AutomationDirect Productivity Suite project: SSW900 adpro (software 4.2.0 (39))
author: fguedez
Rung notation: left to right = series (deeper-indented lines continue the line above), [a | b] = parallel branches, -- = plain wire, BOX.Pin = further input of the box above; 'quoted' = tag name, ? = field left empty; instruction and field names as stored in the project; options that are off are not listed.

HARDWARE
  EtherNet/IP device: E/IP Scanner "SSW900"
    with: SSW900-CETH-W "SSW900"
  Base 1 (5 slots)
    slot 0: P2-550
    slot 1: P2-HSI "P2-HSI-0.1.1"
    slot 2: P2-HSO "P2-HSO-0.1.2"
    slot 3: P2-08SIM

TAGS  (name : type @system ID = initial value)
  'EC Done' : Boolean @C-000183
  'Error Counter' : Int32 @S32-000129
  'IC Done' : Boolean @C-000214
  'Interlock Counter' : Int32 @S32-000131
  'Modbus RTU' : Boolean @C-000266
  'Modbus TCP' : Boolean @C-000304
  'Success Counter' : Int32 @S32-000130
  'Success Done' : Boolean @C-000111
  TimedC : Boolean @C-000225
  'EIP Implicit' : Boolean @C-000428
  'EIP Explicit' : Boolean @C-000429
  'StatusWord P680' : Int16 @S16-000037
  'Optional parameter' : Int16 @S16-000040
  Reserved : Boolean @C-000495
  'StatusWord P680 N2' : Int16 @S16-000041
  'Control Word P684 N2' : Int16 @S16-000042
  'Speed Reference P685 N2' : Int16 @S16-000043
  'Motor Speed P681 N2' : Int16 @S16-000044
  ExplDataIn1 : Array[1] of Int16 @AR1S16-000005
  ExplDataIn2 : Array[1] of Int16 @AR1S16-000006
  ExplDataOut4 : Array[1] of Int16 @AR1S16-000008
  ExplDataOut3 : Array[1] of Int16 @AR1S16-000009
  ExtStst1 : Array[1] of Uint16 @AR1US16-000001
  ExtStst2 : Array[1] of Uint16 @AR1US16-000002
  ExtStst3 : Array[1] of Uint16 @AR1US16-000003
  ExtStst4 : Array[1] of Uint16 @AR1US16-000004
  'Control Word P682' : Uint16 @US16-000014
  'Speed Reference P683' : Int16 @S16-000045
  'Control Word P682 N2' : Uint16 @US16-000015
  'Speed Reference P683 N2' : Int16 @S16-000046
  'Motor Speed HZ' : Int16 @S16-000050
  'Freq CMD Hz' : Int16 @S16-000047
  'Motor Speed HZ N2' : Int16 @S16-000048
  'Freq CMD Hz N2' : Int16 @S16-000049
  'StatusWord P679' : Uint16 @US16-000018
  'Control Word P685' : Uint16 @US16-000016
  'StatusWord P679 N2' : Uint16 @US16-000017
  'Control Word P685 N2' : Uint16 @US16-000019
  'SSW900 Braking' : Boolean @C-000567
  'SSW900 Bypass' : Boolean @C-000568
  'SSW900 Configuration' : Boolean @C-000569
  'SSW900 Fault' : Boolean @C-000570
  'SSW900 Full Voltage' : Boolean @C-000571
  'SSW900 FWD/REV' : Boolean @C-000572
  'SSW900 Initial Test' : Boolean @C-000573
  'SSW900 Jog' : Boolean @C-000574
  'SSW900 Ramp down' : Boolean @C-000575
  'SSW900 Ramp up' : Boolean @C-000576
  'SSW900 Ready' : Boolean @C-000577
  'SSW900 Restart Delay' : Boolean @C-000578
  'SSW900 Start Delay' : Boolean @C-000579
  'SSW900Genearl Disabled' : Boolean @C-000580
  'SSW900 Alarm' : Boolean @C-000581
  'SSW900 Brakingg' : Boolean @C-000582
  'SSW900 Bypasss' : Boolean @C-000583
  'SSW900 Faultt' : Boolean @C-000584
  'SSW900 Full Voltagee' : Boolean @C-000585
  'SSW900 FWD/REVV' : Boolean @C-000586
  'SSW900 Gen Enabled' : Boolean @C-000587
  'SSW900 Initial Testt' : Boolean @C-000588
  'SSW900 Jogg' : Boolean @C-000589
  'SSW900 Ramp downn' : Boolean @C-000590
  'SSW900 Ramp Upp' : Boolean @C-000591
  'SSW900 Remote' : Boolean @C-000592
  'SSW900 Reverse' : Boolean @C-000593
  'SSW900 Running' : Boolean @C-000594
  'SSW900 Toff' : Boolean @C-000595
  'SSW900 Ton' : Boolean @C-000596
  'SSW900 FWD/REV CMD' : Boolean @C-000597
  'SSW900 Gen Enable MD' : Boolean @C-000598
  'SSW900 JOG CMD' : Boolean @C-000599
  'SSW900 LOC/REM CMD' : Boolean @C-000600
  'SSW900 Reset' : Boolean @C-000601
  'SSW900 Start Stop CMD' : Boolean @C-000602
  'SSW900 Braking N2' : Boolean @C-000603
  'SSW900 Bypass N2' : Boolean @C-000604
  'SSW900 Configuration N2' : Boolean @C-000605
  'SSW900 Fault N2' : Boolean @C-000606
  'SSW900 Full Voltage N2' : Boolean @C-000607
  'SSW900 FWD/REV N2' : Boolean @C-000608
  'SSW900 Initial Test N2' : Boolean @C-000609
  'SSW900 Jog N2' : Boolean @C-000610
  'SSW900 Ramp down N2' : Boolean @C-000611
  'SSW900 Ramp up N2' : Boolean @C-000612
  'SSW900 Ready N2' : Boolean @C-000613
  'SSW900 Restart Delay N2' : Boolean @C-000614
  'SSW900 Start Delay N2' : Boolean @C-000615
  'SSW900Genearl Disabled N2' : Boolean @C-000616
  'SSW900 Alarm N2' : Boolean @C-000617
  'SSW900 Brakingg N2' : Boolean @C-000618
  'SSW900 Bypasss N2' : Boolean @C-000619
  'SSW900 Faultt N2' : Boolean @C-000620
  'SSW900 Full Voltagee N2' : Boolean @C-000621
  'SSW900 FWD/REVV N2' : Boolean @C-000622
  'SSW900 Gen Enabled N2' : Boolean @C-000623
  'SSW900 Initial Testt N2' : Boolean @C-000624
  'SSW900 Jogg N2' : Boolean @C-000625
  'SSW900 Ramp downn N2' : Boolean @C-000626
  'SSW900 Ramp Upp N2' : Boolean @C-000627
  'SSW900 Remote N2' : Boolean @C-000628
  'SSW900 Reverse N2' : Boolean @C-000629
  'SSW900 Running N2' : Boolean @C-000630
  'SSW900 Toff N2' : Boolean @C-000631
  'SSW900 Ton N2' : Boolean @C-000632
  'SSW900 FWD/REV CMD N2' : Boolean @C-000633
  'SSW900 Gen Enable MD N2' : Boolean @C-000634
  'SSW900 JOG CMD N2' : Boolean @C-000635
  'SSW900 Reset N2' : Boolean @C-000636
  'SSW900 Start Stop CMD N2' : Boolean @C-000637
  'SSW900 Data In' : Array[1] of Uint16 @AR1US16-000005
  'SSW900 Data Out' : Array[1] of Uint16 @AR1US16-000006
  Test : Array[16] of Boolean @AR1C-000001

SYSTEM TAGS USED OR MAPPED TO MODBUS
  'Always Off Bit' : Boolean @SBR-001002  // always off
  EXp1 : EMSG @SSTRUC-000031  // System Structure for EtherNet/IP Explicit Message
  EXp3 : EMSG @SSTRUC-000033  // System Structure for EtherNet/IP Explicit Message
  'SSW900 Node1 Read' : MRX @SSTRUC-000044  // System Structure for Modbus Read
  'SSW900 Node1 Write' : MWX @SSTRUC-000045  // System Structure for Modbus Write
  'SSW900 Node2 Read' : MRX @SSTRUC-000046  // System Structure for Modbus Read
  'SSW900 Node2 Write' : MWX @SSTRUC-000047  // System Structure for Modbus Write

TASK Main  (Run Every Scan)
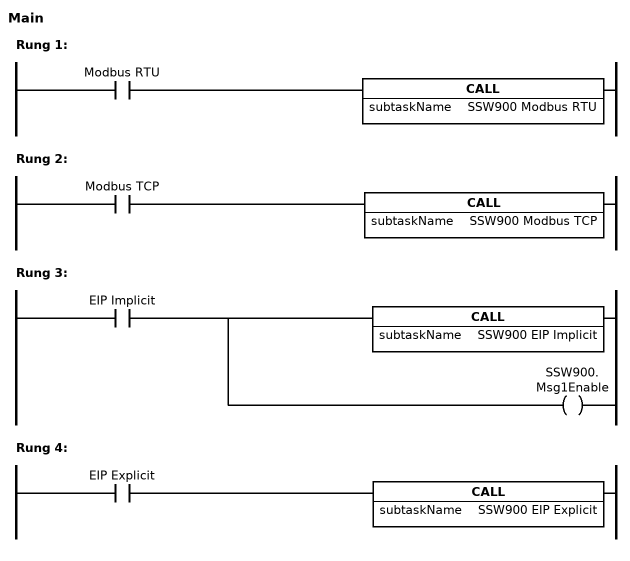
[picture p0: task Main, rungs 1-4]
Rung 1:
  NO('Modbus RTU') CALL('SSW900 Modbus RTU')
Rung 2:
  NO('Modbus TCP') CALL('SSW900 Modbus TCP')
Rung 3:
  NO('EIP Implicit') [CALL('SSW900 EIP Implicit') | OUT(SSW900.Msg1Enable)]
Rung 4:
  NO('EIP Explicit') CALL('SSW900 EIP Explicit')

TASK 'SSW900 Modbus RTU'  (Run When Called)
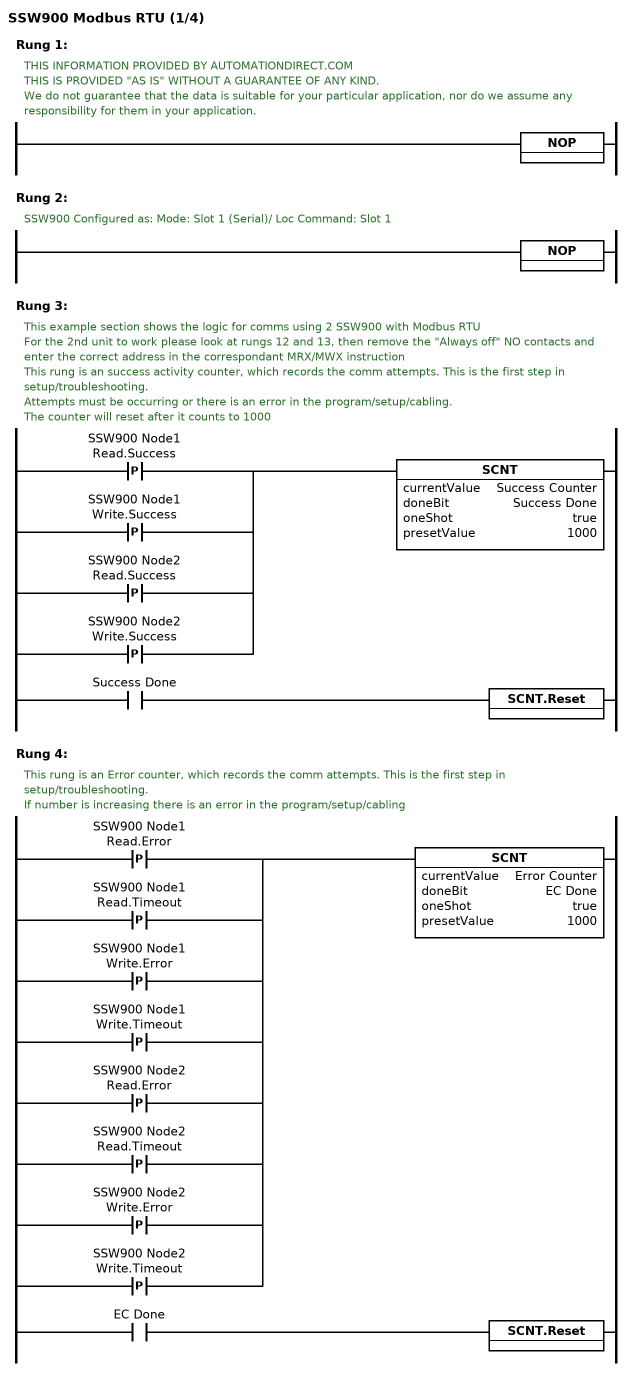
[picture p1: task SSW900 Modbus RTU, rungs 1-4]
Rung 1:
  // THIS INFORMATION PROVIDED BY AUTOMATIONDIRECT.COM
  // THIS IS PROVIDED "AS IS" WITHOUT A GUARANTEE OF ANY KIND.
  // We do not guarantee that the data is suitable for your particular application, nor do we assume any responsibility for them in your application.
  NOP()
Rung 2:
  // SSW900 Configured as: Mode: Slot 1 (Serial)/ Loc Command: Slot 1
  NOP()
Rung 3:
  // This example section shows the logic for comms using 2 SSW900 with Modbus RTU
  // For the 2nd unit to work please look at rungs 12 and 13, then remove the "Always off" NO contacts and enter the correct address in the correspondant MRX/MWX instruction
  // This rung is an success activity counter, which records the comm attempts. This is the first step in setup/troubleshooting.
  // Attempts must be occurring or there is an error in the program/setup/cabling.
  // The counter will reset after it counts to 1000
  [ NOE('SSW900 Node1 Read.Success', rising)
    | NOE('SSW900 Node1 Write.Success', rising)
    | NOE('SSW900 Node2 Read.Success', rising)
    | NOE('SSW900 Node2 Write.Success', rising) ]
    SCNT(currentValue='Success Counter', doneBit='Success Done', oneShot, presetValue=1000)
  NO('Success Done') SCNT.Reset
Rung 4:
  // This rung is an Error counter, which records the comm attempts. This is the first step in setup/troubleshooting.
  // If number is increasing there is an error in the program/setup/cabling
  [ NOE('SSW900 Node1 Read.Error', rising)
    | NOE('SSW900 Node1 Read.Timeout', rising)
    | NOE('SSW900 Node1 Write.Error', rising)
    | NOE('SSW900 Node1 Write.Timeout', rising)
    | NOE('SSW900 Node2 Read.Error', rising)
    | NOE('SSW900 Node2 Read.Timeout', rising)
    | NOE('SSW900 Node2 Write.Error', rising)
    | NOE('SSW900 Node2 Write.Timeout', rising) ]
    SCNT(currentValue='Error Counter', doneBit='EC Done', oneShot, presetValue=1000)
  NO('EC Done') SCNT.Reset
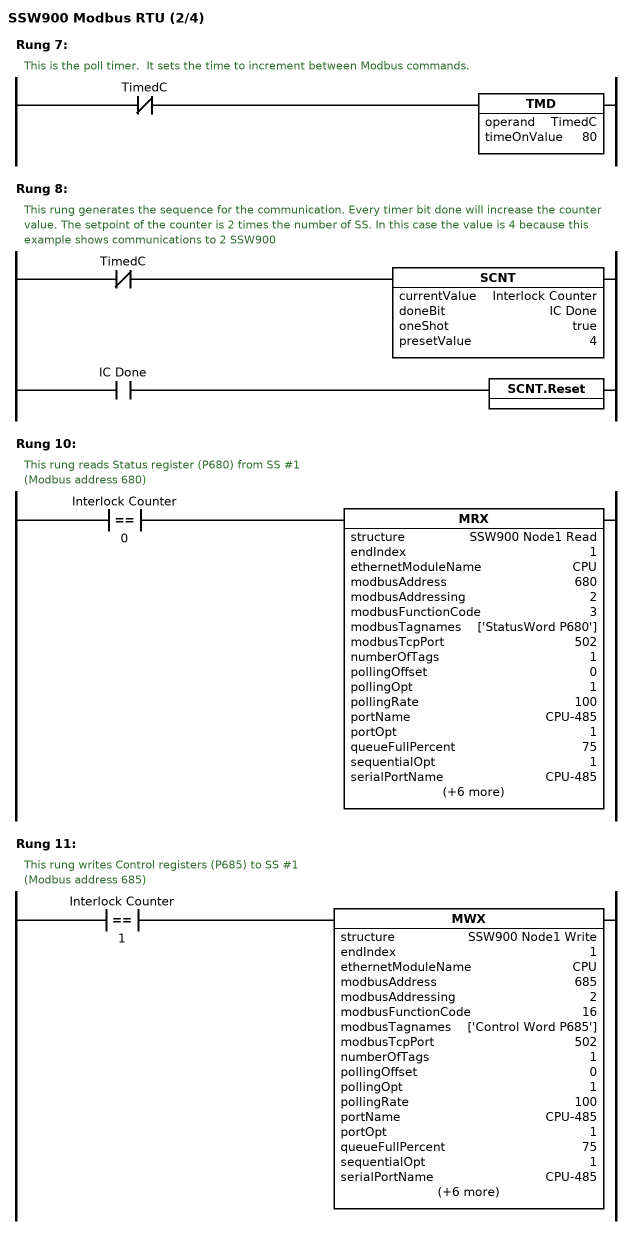
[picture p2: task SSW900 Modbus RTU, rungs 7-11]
Rung 7:
  // This is the poll timer.  It sets the time to increment between Modbus commands.
  NC(TimedC) TMD(TimedC, timeOnValue=80)
Rung 8:
  // This rung generates the sequence for the communication. Every timer bit done will increase the counter value. The setpoint of the counter is 2 times the number of SS. In this case the value is 4 because this example shows communications to 2 SSW900
  NC(TimedC) SCNT(currentValue='Interlock Counter', doneBit='IC Done', oneShot, presetValue=4)
  NO('IC Done') SCNT.Reset
Rung 10:
  // This rung reads Status register (P680) from SS #1
  // (Modbus address 680)
  COMP('Interlock Counter' = 0)
    MRX(structure='SSW900 Node1 Read', endIndex=1, ethernetModuleName=CPU, modbusAddress=680, modbusAddressing=2, modbusFunctionCode=3, modbusTagnames=['StatusWord P680'], modbusTcpPort=502, numberOfTags=1, pollingOffset=0, pollingOpt=1, pollingRate=100, portName=CPU-485, portOpt=1, queueFullPercent=75, sequentialOpt=1, serialPortName=CPU-485, slaveEthernetNodeNum=255, slaveIpAddress=10.10.112.59, slaveSerialNodeNum=1, startingIndex=1, stringLength=2, wordSwap)
Rung 11:
  // This rung writes Control registers (P685) to SS #1
  // (Modbus address 685)
  COMP('Interlock Counter' = 1)
    MWX(structure='SSW900 Node1 Write', endIndex=1, ethernetModuleName=CPU, modbusAddress=685, modbusAddressing=2, modbusFunctionCode=16, modbusTagnames=['Control Word P685'], modbusTcpPort=502, numberOfTags=1, pollingOffset=0, pollingOpt=1, pollingRate=100, portName=CPU-485, portOpt=1, queueFullPercent=75, sequentialOpt=1, serialPortName=CPU-485, slaveEthernetNodeNum=255, slaveIpAddress=10.10.112.59, slaveSerialNodeNum=1, startingIndex=1, stringLength=2, wordSwap)
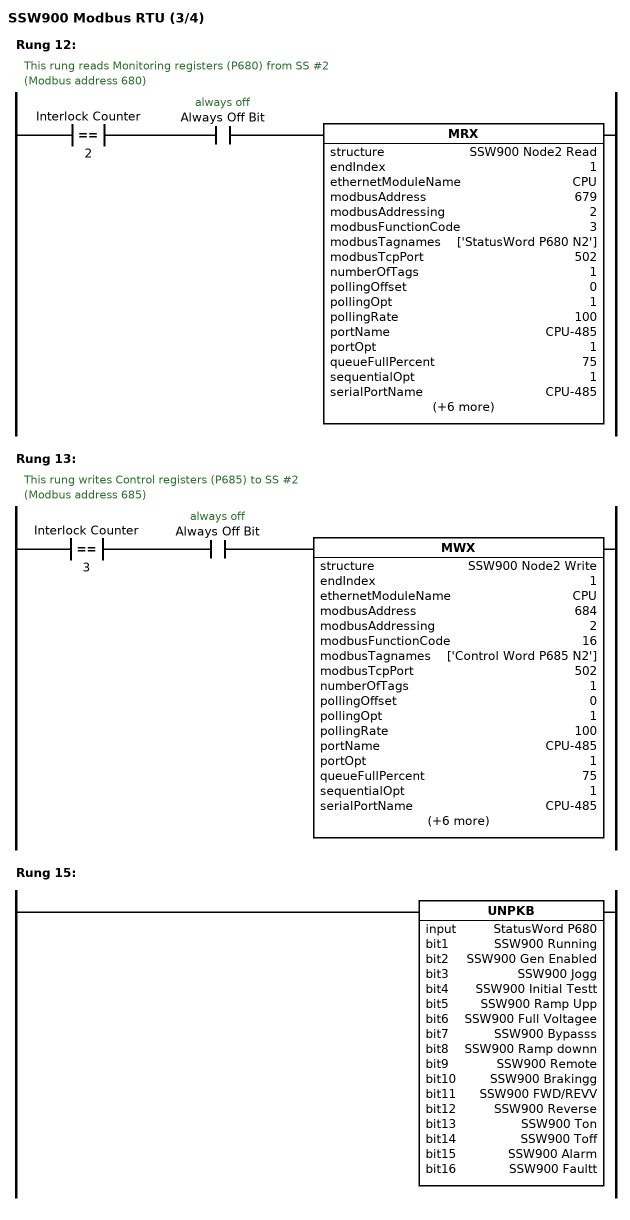
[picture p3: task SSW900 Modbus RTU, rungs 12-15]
Rung 12:
  // This rung reads Monitoring registers (P680) from SS #2
  // (Modbus address 680)
  COMP('Interlock Counter' = 2) NO('Always Off Bit')
    MRX(structure='SSW900 Node2 Read', endIndex=1, ethernetModuleName=CPU, modbusAddress=679, modbusAddressing=2, modbusFunctionCode=3, modbusTagnames=['StatusWord P680 N2'], modbusTcpPort=502, numberOfTags=1, pollingOffset=0, pollingOpt=1, pollingRate=100, portName=CPU-485, portOpt=1, queueFullPercent=75, sequentialOpt=1, serialPortName=CPU-485, slaveEthernetNodeNum=255, slaveIpAddress=10.10.112.59, slaveSerialNodeNum=2, startingIndex=1, stringLength=2, wordSwap)
Rung 13:
  // This rung writes Control registers (P685) to SS #2
  // (Modbus address 685)
  COMP('Interlock Counter' = 3) NO('Always Off Bit')
    MWX(structure='SSW900 Node2 Write', endIndex=1, ethernetModuleName=CPU, modbusAddress=684, modbusAddressing=2, modbusFunctionCode=16, modbusTagnames=['Control Word P685 N2'], modbusTcpPort=502, numberOfTags=1, pollingOffset=0, pollingOpt=1, pollingRate=100, portName=CPU-485, portOpt=1, queueFullPercent=75, sequentialOpt=1, serialPortName=CPU-485, slaveEthernetNodeNum=255, slaveIpAddress=10.10.112.59, slaveSerialNodeNum=2, startingIndex=1, stringLength=2, wordSwap)
Rung 15:
  UNPKB(input='StatusWord P680', bit1='SSW900 Running', bit2='SSW900 Gen Enabled', bit3='SSW900 Jogg', bit4='SSW900 Initial Testt', bit5='SSW900 Ramp Upp', bit6='SSW900 Full Voltagee', bit7='SSW900 Bypasss', bit8='SSW900 Ramp downn', bit9='SSW900 Remote', bit10='SSW900 Brakingg', bit11='SSW900 FWD/REVV', bit12='SSW900 Reverse', bit13='SSW900 Ton', bit14='SSW900 Toff', bit15='SSW900 Alarm', bit16='SSW900 Faultt')
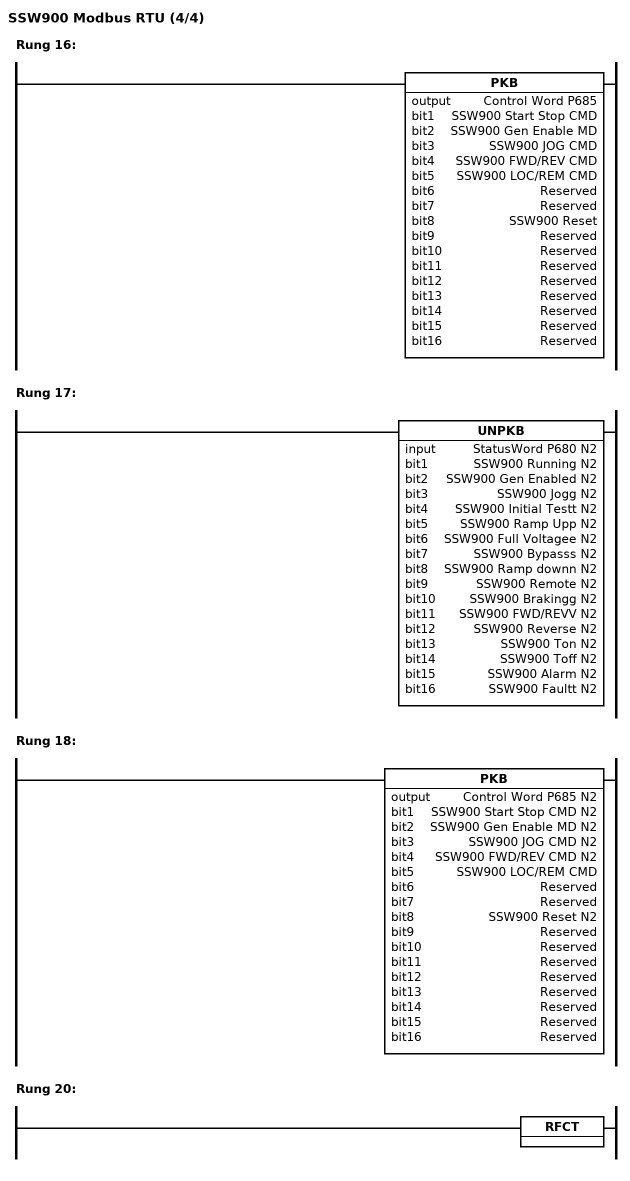
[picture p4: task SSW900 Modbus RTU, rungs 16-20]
Rung 16:
  PKB(output='Control Word P685', bit1='SSW900 Start Stop CMD', bit2='SSW900 Gen Enable MD', bit3='SSW900 JOG CMD', bit4='SSW900 FWD/REV CMD', bit5='SSW900 LOC/REM CMD', bit6=Reserved, bit7=Reserved, bit8='SSW900 Reset', bit9=Reserved, bit10=Reserved, bit11=Reserved, bit12=Reserved, bit13=Reserved, bit14=Reserved, bit15=Reserved, bit16=Reserved)
Rung 17:
  UNPKB(input='StatusWord P680 N2', bit1='SSW900 Running N2', bit2='SSW900 Gen Enabled N2', bit3='SSW900 Jogg N2', bit4='SSW900 Initial Testt N2', bit5='SSW900 Ramp Upp N2', bit6='SSW900 Full Voltagee N2', bit7='SSW900 Bypasss N2', bit8='SSW900 Ramp downn N2', bit9='SSW900 Remote N2', bit10='SSW900 Brakingg N2', bit11='SSW900 FWD/REVV N2', bit12='SSW900 Reverse N2', bit13='SSW900 Ton N2', bit14='SSW900 Toff N2', bit15='SSW900 Alarm N2', bit16='SSW900 Faultt N2')
Rung 18:
  PKB(output='Control Word P685 N2', bit1='SSW900 Start Stop CMD N2', bit2='SSW900 Gen Enable MD N2', bit3='SSW900 JOG CMD N2', bit4='SSW900 FWD/REV CMD N2', bit5='SSW900 LOC/REM CMD', bit6=Reserved, bit7=Reserved, bit8='SSW900 Reset N2', bit9=Reserved, bit10=Reserved, bit11=Reserved, bit12=Reserved, bit13=Reserved, bit14=Reserved, bit15=Reserved, bit16=Reserved)
Rung 20:
  RFCT()

TASK 'SSW900 Modbus TCP'  (Run When Called)
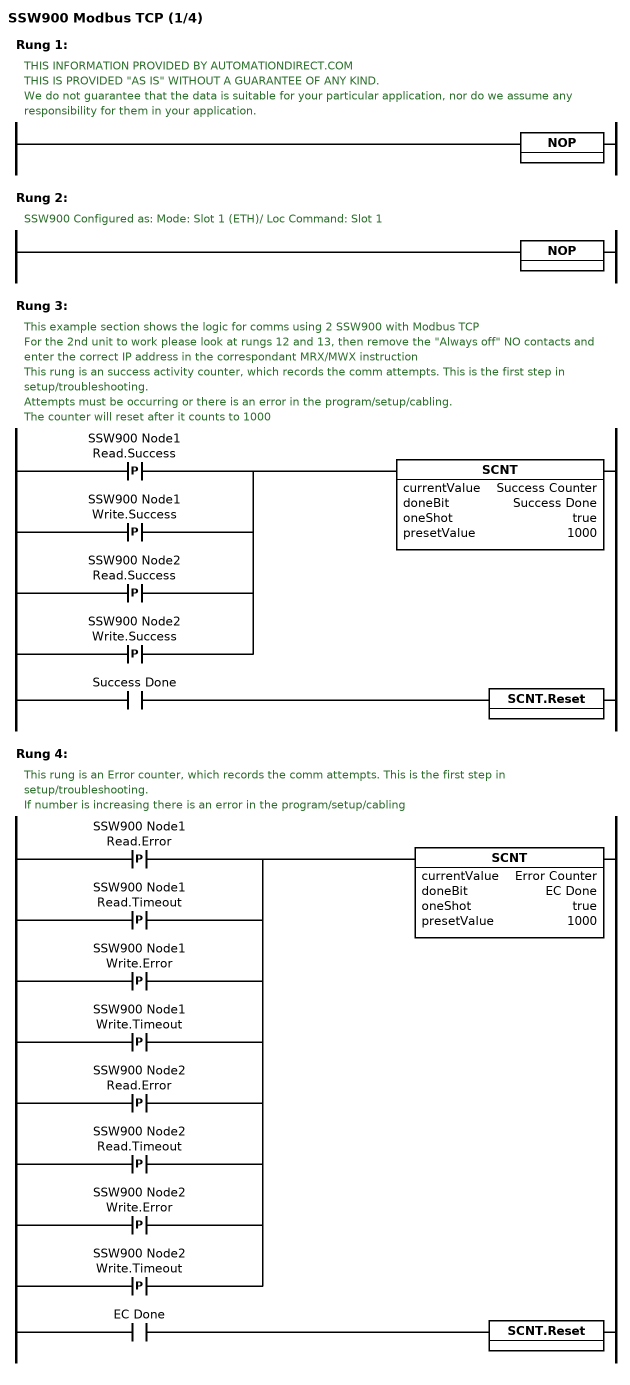
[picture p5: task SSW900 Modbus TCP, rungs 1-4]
Rung 1:
  // THIS INFORMATION PROVIDED BY AUTOMATIONDIRECT.COM
  // THIS IS PROVIDED "AS IS" WITHOUT A GUARANTEE OF ANY KIND.
  // We do not guarantee that the data is suitable for your particular application, nor do we assume any responsibility for them in your application.
  NOP()
Rung 2:
  // SSW900 Configured as: Mode: Slot 1 (ETH)/ Loc Command: Slot 1
  NOP()
Rung 3:
  // This example section shows the logic for comms using 2 SSW900 with Modbus TCP
  // For the 2nd unit to work please look at rungs 12 and 13, then remove the "Always off" NO contacts and enter the correct IP address in the correspondant MRX/MWX instruction
  // This rung is an success activity counter, which records the comm attempts. This is the first step in setup/troubleshooting.
  // Attempts must be occurring or there is an error in the program/setup/cabling.
  // The counter will reset after it counts to 1000
  [ NOE('SSW900 Node1 Read.Success', rising)
    | NOE('SSW900 Node1 Write.Success', rising)
    | NOE('SSW900 Node2 Read.Success', rising)
    | NOE('SSW900 Node2 Write.Success', rising) ]
    SCNT(currentValue='Success Counter', doneBit='Success Done', oneShot, presetValue=1000)
  NO('Success Done') SCNT.Reset
Rung 4:
  // This rung is an Error counter, which records the comm attempts. This is the first step in setup/troubleshooting.
  // If number is increasing there is an error in the program/setup/cabling
  [ NOE('SSW900 Node1 Read.Error', rising)
    | NOE('SSW900 Node1 Read.Timeout', rising)
    | NOE('SSW900 Node1 Write.Error', rising)
    | NOE('SSW900 Node1 Write.Timeout', rising)
    | NOE('SSW900 Node2 Read.Error', rising)
    | NOE('SSW900 Node2 Read.Timeout', rising)
    | NOE('SSW900 Node2 Write.Error', rising)
    | NOE('SSW900 Node2 Write.Timeout', rising) ]
    SCNT(currentValue='Error Counter', doneBit='EC Done', oneShot, presetValue=1000)
  NO('EC Done') SCNT.Reset
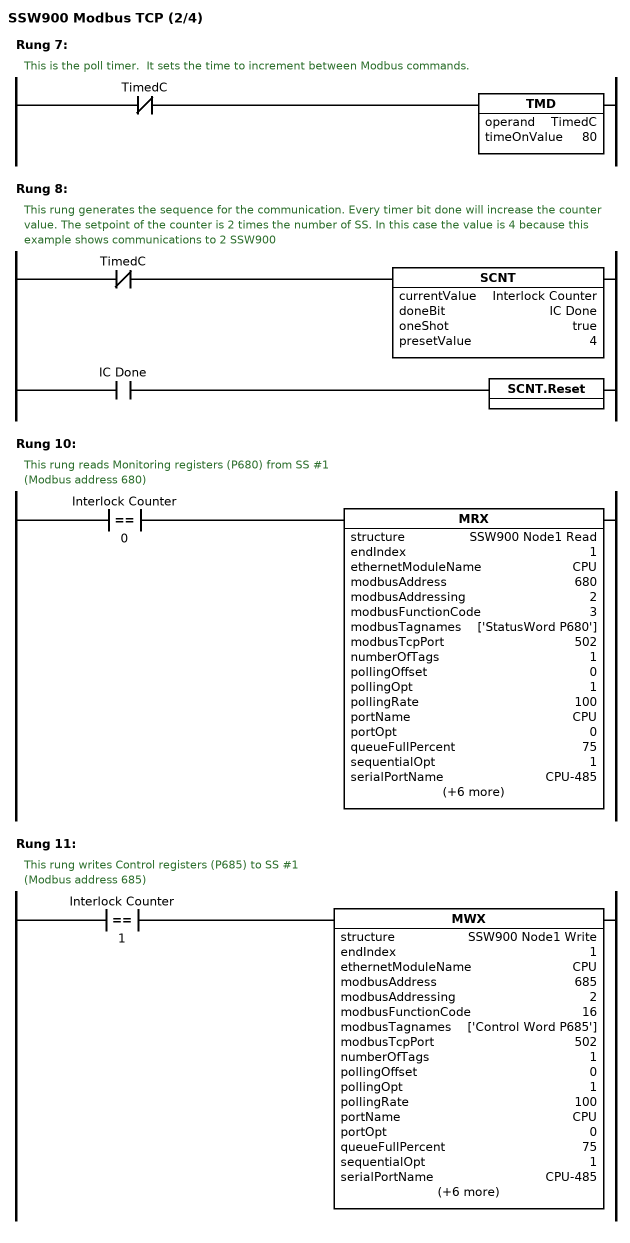
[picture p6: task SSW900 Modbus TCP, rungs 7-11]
Rung 7:
  // This is the poll timer.  It sets the time to increment between Modbus commands.
  NC(TimedC) TMD(TimedC, timeOnValue=80)
Rung 8:
  // This rung generates the sequence for the communication. Every timer bit done will increase the counter value. The setpoint of the counter is 2 times the number of SS. In this case the value is 4 because this example shows communications to 2 SSW900
  NC(TimedC) SCNT(currentValue='Interlock Counter', doneBit='IC Done', oneShot, presetValue=4)
  NO('IC Done') SCNT.Reset
Rung 10:
  // This rung reads Monitoring registers (P680) from SS #1
  // (Modbus address 680)
  COMP('Interlock Counter' = 0)
    MRX(structure='SSW900 Node1 Read', endIndex=1, ethernetModuleName=CPU, modbusAddress=680, modbusAddressing=2, modbusFunctionCode=3, modbusTagnames=['StatusWord P680'], modbusTcpPort=502, numberOfTags=1, pollingOffset=0, pollingOpt=1, pollingRate=100, portName=CPU, portOpt=0, queueFullPercent=75, sequentialOpt=1, serialPortName=CPU-485, slaveEthernetNodeNum=255, slaveIpAddress=10.10.112.59, slaveSerialNodeNum=1, startingIndex=1, stringLength=2, wordSwap)
Rung 11:
  // This rung writes Control registers (P685) to SS #1
  // (Modbus address 685)
  COMP('Interlock Counter' = 1)
    MWX(structure='SSW900 Node1 Write', endIndex=1, ethernetModuleName=CPU, modbusAddress=685, modbusAddressing=2, modbusFunctionCode=16, modbusTagnames=['Control Word P685'], modbusTcpPort=502, numberOfTags=1, pollingOffset=0, pollingOpt=1, pollingRate=100, portName=CPU, portOpt=0, queueFullPercent=75, sequentialOpt=1, serialPortName=CPU-485, slaveEthernetNodeNum=255, slaveIpAddress=10.10.112.59, slaveSerialNodeNum=1, startingIndex=1, stringLength=2, wordSwap)
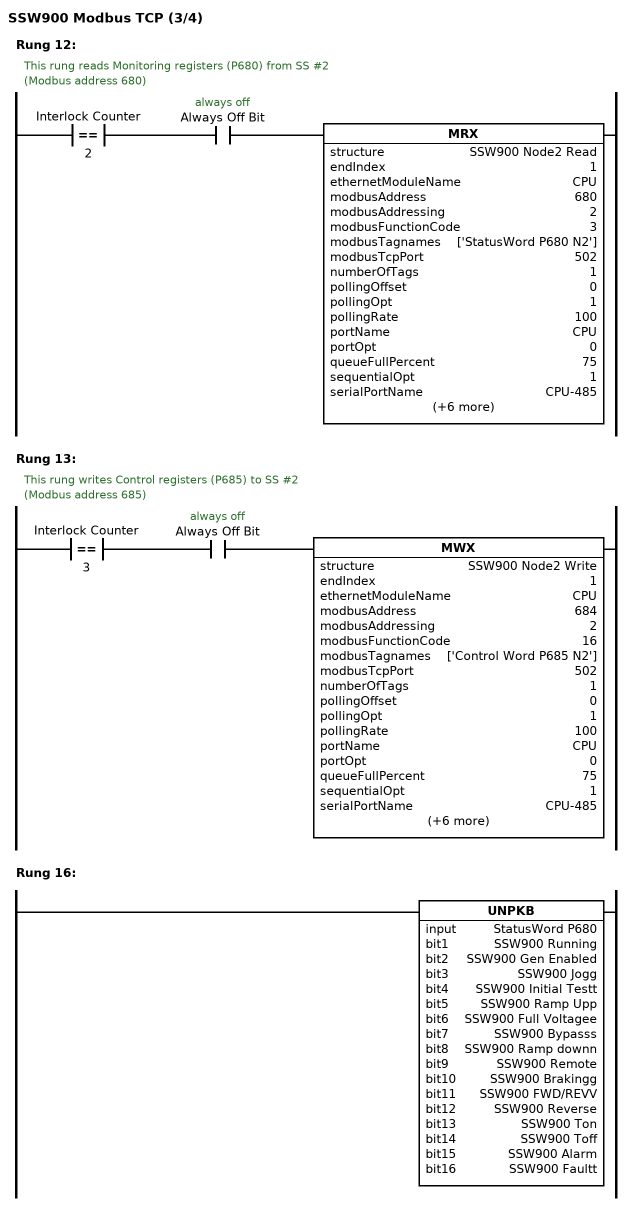
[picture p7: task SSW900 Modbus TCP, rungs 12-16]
Rung 12:
  // This rung reads Monitoring registers (P680) from SS #2
  // (Modbus address 680)
  COMP('Interlock Counter' = 2) NO('Always Off Bit')
    MRX(structure='SSW900 Node2 Read', endIndex=1, ethernetModuleName=CPU, modbusAddress=680, modbusAddressing=2, modbusFunctionCode=3, modbusTagnames=['StatusWord P680 N2'], modbusTcpPort=502, numberOfTags=1, pollingOffset=0, pollingOpt=1, pollingRate=100, portName=CPU, portOpt=0, queueFullPercent=75, sequentialOpt=1, serialPortName=CPU-485, slaveEthernetNodeNum=255, slaveIpAddress=10.10.112.59, slaveSerialNodeNum=1, startingIndex=1, stringLength=2, wordSwap)
Rung 13:
  // This rung writes Control registers (P685) to SS #2
  // (Modbus address 685)
  COMP('Interlock Counter' = 3) NO('Always Off Bit')
    MWX(structure='SSW900 Node2 Write', endIndex=1, ethernetModuleName=CPU, modbusAddress=684, modbusAddressing=2, modbusFunctionCode=16, modbusTagnames=['Control Word P685 N2'], modbusTcpPort=502, numberOfTags=1, pollingOffset=0, pollingOpt=1, pollingRate=100, portName=CPU, portOpt=0, queueFullPercent=75, sequentialOpt=1, serialPortName=CPU-485, slaveEthernetNodeNum=255, slaveIpAddress=10.10.112.59, slaveSerialNodeNum=1, startingIndex=1, stringLength=2, wordSwap)
Rung 16:
  UNPKB(input='StatusWord P680', bit1='SSW900 Running', bit2='SSW900 Gen Enabled', bit3='SSW900 Jogg', bit4='SSW900 Initial Testt', bit5='SSW900 Ramp Upp', bit6='SSW900 Full Voltagee', bit7='SSW900 Bypasss', bit8='SSW900 Ramp downn', bit9='SSW900 Remote', bit10='SSW900 Brakingg', bit11='SSW900 FWD/REVV', bit12='SSW900 Reverse', bit13='SSW900 Ton', bit14='SSW900 Toff', bit15='SSW900 Alarm', bit16='SSW900 Faultt')
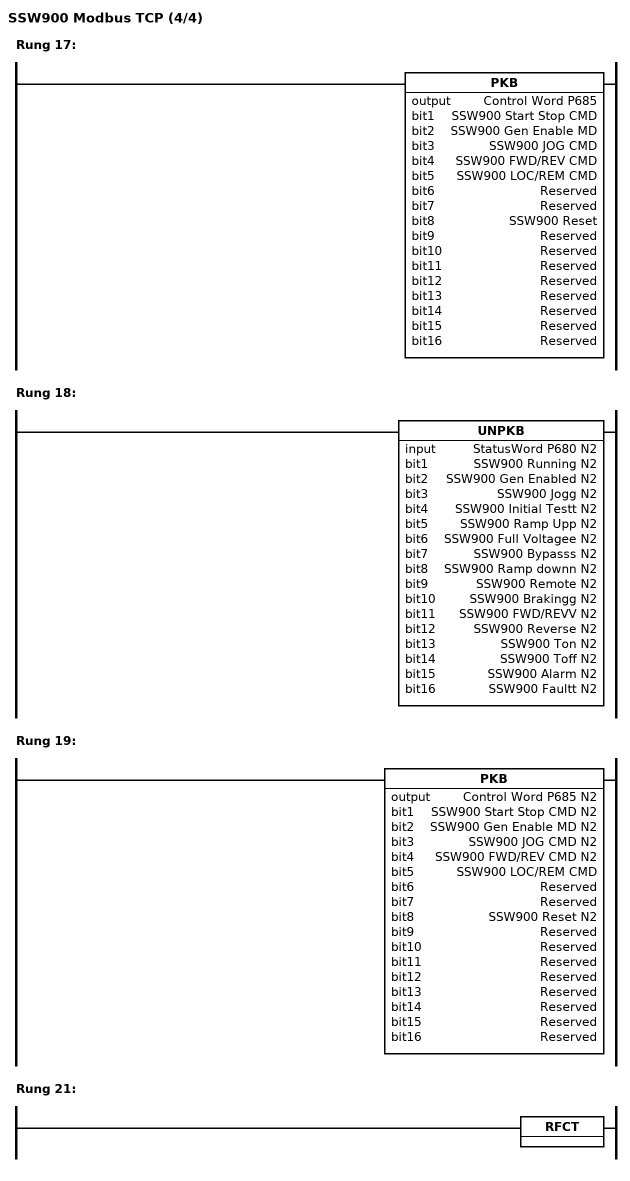
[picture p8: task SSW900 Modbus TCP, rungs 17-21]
Rung 17:
  PKB(output='Control Word P685', bit1='SSW900 Start Stop CMD', bit2='SSW900 Gen Enable MD', bit3='SSW900 JOG CMD', bit4='SSW900 FWD/REV CMD', bit5='SSW900 LOC/REM CMD', bit6=Reserved, bit7=Reserved, bit8='SSW900 Reset', bit9=Reserved, bit10=Reserved, bit11=Reserved, bit12=Reserved, bit13=Reserved, bit14=Reserved, bit15=Reserved, bit16=Reserved)
Rung 18:
  UNPKB(input='StatusWord P680 N2', bit1='SSW900 Running N2', bit2='SSW900 Gen Enabled N2', bit3='SSW900 Jogg N2', bit4='SSW900 Initial Testt N2', bit5='SSW900 Ramp Upp N2', bit6='SSW900 Full Voltagee N2', bit7='SSW900 Bypasss N2', bit8='SSW900 Ramp downn N2', bit9='SSW900 Remote N2', bit10='SSW900 Brakingg N2', bit11='SSW900 FWD/REVV N2', bit12='SSW900 Reverse N2', bit13='SSW900 Ton N2', bit14='SSW900 Toff N2', bit15='SSW900 Alarm N2', bit16='SSW900 Faultt N2')
Rung 19:
  PKB(output='Control Word P685 N2', bit1='SSW900 Start Stop CMD N2', bit2='SSW900 Gen Enable MD N2', bit3='SSW900 JOG CMD N2', bit4='SSW900 FWD/REV CMD N2', bit5='SSW900 LOC/REM CMD', bit6=Reserved, bit7=Reserved, bit8='SSW900 Reset N2', bit9=Reserved, bit10=Reserved, bit11=Reserved, bit12=Reserved, bit13=Reserved, bit14=Reserved, bit15=Reserved, bit16=Reserved)
Rung 21:
  RFCT()

TASK 'SSW900 EIP Implicit'  (Run When Called)
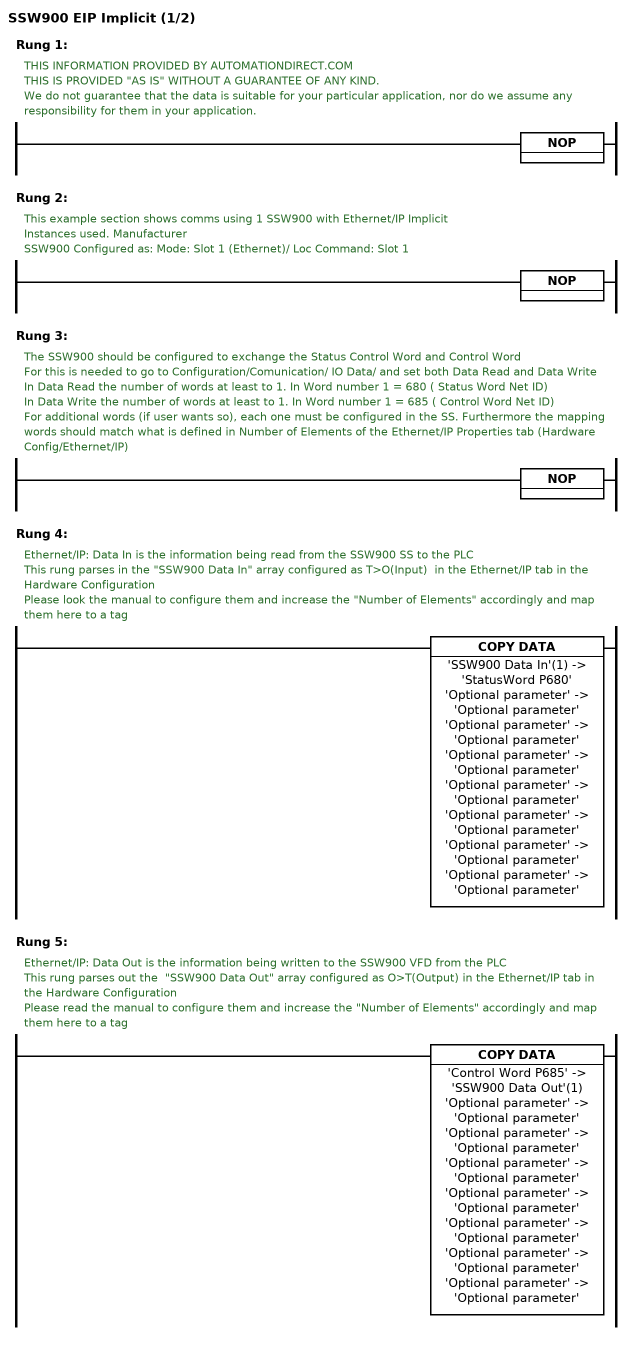
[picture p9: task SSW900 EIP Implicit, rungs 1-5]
Rung 1:
  // THIS INFORMATION PROVIDED BY AUTOMATIONDIRECT.COM
  // THIS IS PROVIDED "AS IS" WITHOUT A GUARANTEE OF ANY KIND.
  // We do not guarantee that the data is suitable for your particular application, nor do we assume any responsibility for them in your application.
  NOP()
Rung 2:
  // This example section shows comms using 1 SSW900 with Ethernet/IP Implicit
  // Instances used. Manufacturer
  // SSW900 Configured as: Mode: Slot 1 (Ethernet)/ Loc Command: Slot 1
  NOP()
Rung 3:
  // The SSW900 should be configured to exchange the Status Control Word and Control Word
  // For this is needed to go to Configuration/Comunication/ IO Data/ and set both Data Read and Data Write
  // In Data Read the number of words at least to 1. In Word number 1 = 680 ( Status Word Net ID)
  // In Data Write the number of words at least to 1. In Word number 1 = 685 ( Control Word Net ID)
  // For additional words (if user wants so), each one must be configured in the SS. Furthermore the mapping words should match what is defined in Number of Elements of the Ethernet/IP Properties tab (Hardware Config/Ethernet/IP)
  NOP()
Rung 4:
  // Ethernet/IP: Data In is the information being read from the SSW900 SS to the PLC
  // This rung parses in the "SSW900 Data In" array configured as T>O(Input)  in the Ethernet/IP tab in the Hardware Configuration
  // Please look the manual to configure them and increase the "Number of Elements" accordingly and map them here to a tag
  CPY('SSW900 Data In'(1) -> 'StatusWord P680', 'Optional parameter' -> 'Optional parameter', 'Optional parameter' -> 'Optional parameter', 'Optional parameter' -> 'Optional parameter', 'Optional parameter' -> 'Optional parameter', 'Optional parameter' -> 'Optional parameter', 'Optional parameter' -> 'Optional parameter', 'Optional parameter' -> 'Optional parameter')
Rung 5:
  // Ethernet/IP: Data Out is the information being written to the SSW900 VFD from the PLC
  // This rung parses out the  "SSW900 Data Out" array configured as O>T(Output) in the Ethernet/IP tab in the Hardware Configuration
  // Please read the manual to configure them and increase the "Number of Elements" accordingly and map them here to a tag
  CPY('Control Word P685' -> 'SSW900 Data Out'(1), 'Optional parameter' -> 'Optional parameter', 'Optional parameter' -> 'Optional parameter', 'Optional parameter' -> 'Optional parameter', 'Optional parameter' -> 'Optional parameter', 'Optional parameter' -> 'Optional parameter', 'Optional parameter' -> 'Optional parameter', 'Optional parameter' -> 'Optional parameter')
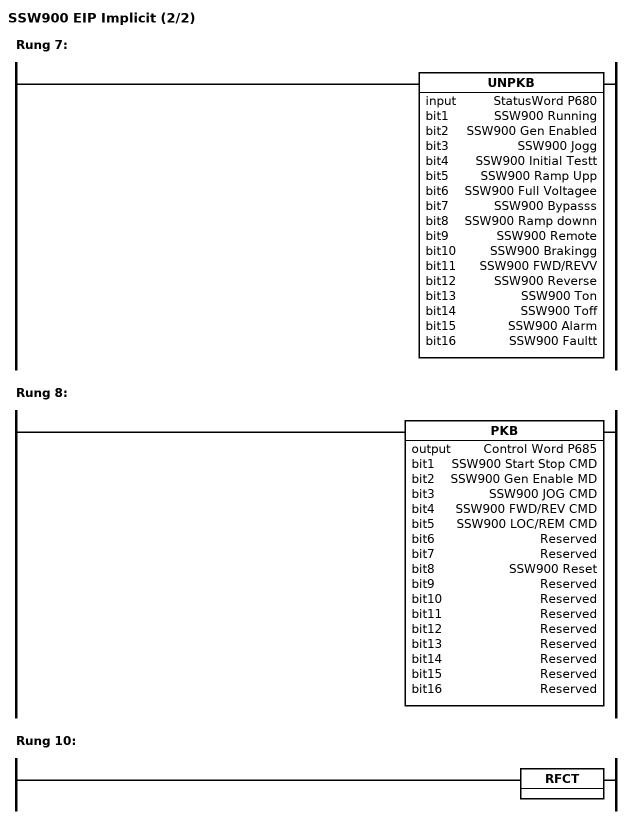
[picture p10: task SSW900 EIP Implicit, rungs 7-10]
Rung 7:
  UNPKB(input='StatusWord P680', bit1='SSW900 Running', bit2='SSW900 Gen Enabled', bit3='SSW900 Jogg', bit4='SSW900 Initial Testt', bit5='SSW900 Ramp Upp', bit6='SSW900 Full Voltagee', bit7='SSW900 Bypasss', bit8='SSW900 Ramp downn', bit9='SSW900 Remote', bit10='SSW900 Brakingg', bit11='SSW900 FWD/REVV', bit12='SSW900 Reverse', bit13='SSW900 Ton', bit14='SSW900 Toff', bit15='SSW900 Alarm', bit16='SSW900 Faultt')
Rung 8:
  PKB(output='Control Word P685', bit1='SSW900 Start Stop CMD', bit2='SSW900 Gen Enable MD', bit3='SSW900 JOG CMD', bit4='SSW900 FWD/REV CMD', bit5='SSW900 LOC/REM CMD', bit6=Reserved, bit7=Reserved, bit8='SSW900 Reset', bit9=Reserved, bit10=Reserved, bit11=Reserved, bit12=Reserved, bit13=Reserved, bit14=Reserved, bit15=Reserved, bit16=Reserved)
Rung 10:
  RFCT()

TASK 'SSW900 EIP Explicit'  (Run When Called)
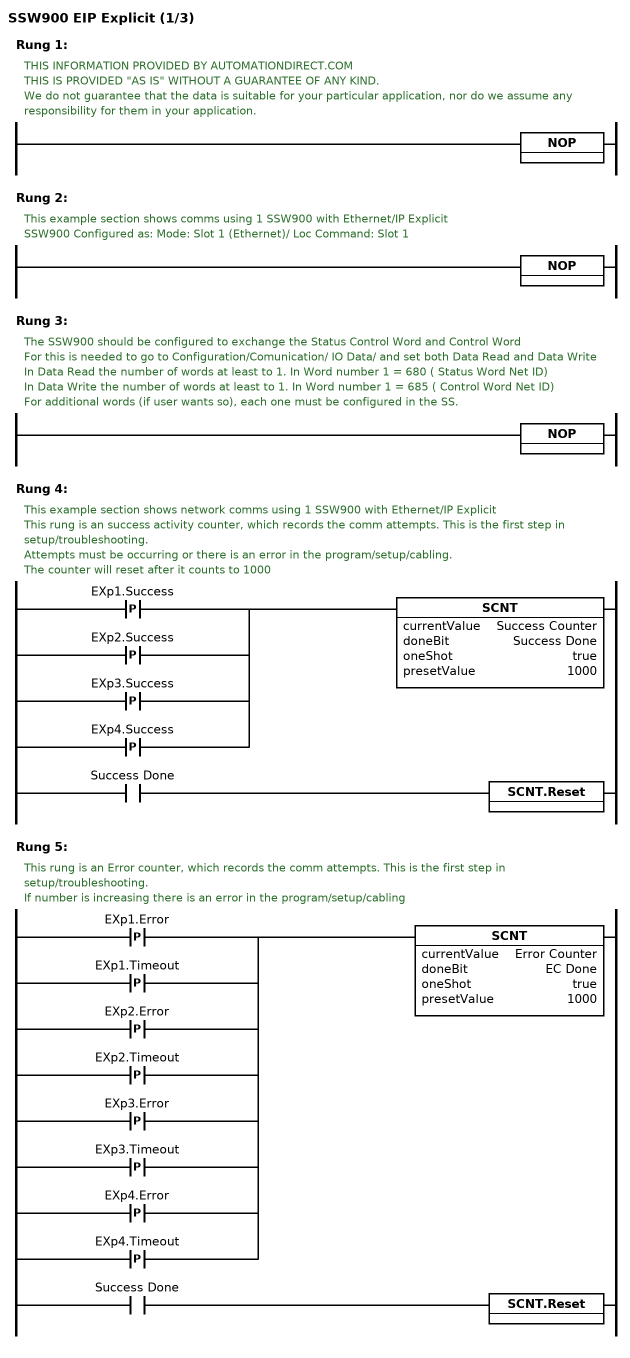
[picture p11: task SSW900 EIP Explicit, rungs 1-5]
Rung 1:
  // THIS INFORMATION PROVIDED BY AUTOMATIONDIRECT.COM
  // THIS IS PROVIDED "AS IS" WITHOUT A GUARANTEE OF ANY KIND.
  // We do not guarantee that the data is suitable for your particular application, nor do we assume any responsibility for them in your application.
  NOP()
Rung 2:
  // This example section shows comms using 1 SSW900 with Ethernet/IP Explicit
  // SSW900 Configured as: Mode: Slot 1 (Ethernet)/ Loc Command: Slot 1
  NOP()
Rung 3:
  // The SSW900 should be configured to exchange the Status Control Word and Control Word
  // For this is needed to go to Configuration/Comunication/ IO Data/ and set both Data Read and Data Write
  // In Data Read the number of words at least to 1. In Word number 1 = 680 ( Status Word Net ID)
  // In Data Write the number of words at least to 1. In Word number 1 = 685 ( Control Word Net ID)
  // For additional words (if user wants so), each one must be configured in the SS.
  NOP()
Rung 4:
  // This example section shows network comms using 1 SSW900 with Ethernet/IP Explicit
  // This rung is an success activity counter, which records the comm attempts. This is the first step in setup/troubleshooting.
  // Attempts must be occurring or there is an error in the program/setup/cabling.
  // The counter will reset after it counts to 1000
  [NOE(EXp1.Success, rising) | NOE(EXp2.Success, rising) | NOE(EXp3.Success, rising) | NOE(EXp4.Success, rising)]
    SCNT(currentValue='Success Counter', doneBit='Success Done', oneShot, presetValue=1000)
  NO('Success Done') SCNT.Reset
Rung 5:
  // This rung is an Error counter, which records the comm attempts. This is the first step in setup/troubleshooting.
  // If number is increasing there is an error in the program/setup/cabling
  [ NOE(EXp1.Error, rising)
    | NOE(EXp1.Timeout, rising)
    | NOE(EXp2.Error, rising)
    | NOE(EXp2.Timeout, rising)
    | NOE(EXp3.Error, rising)
    | NOE(EXp3.Timeout, rising)
    | NOE(EXp4.Error, rising)
    | NOE(EXp4.Timeout, rising) ]
    SCNT(currentValue='Error Counter', doneBit='EC Done', oneShot, presetValue=1000)
  NO('Success Done') SCNT.Reset
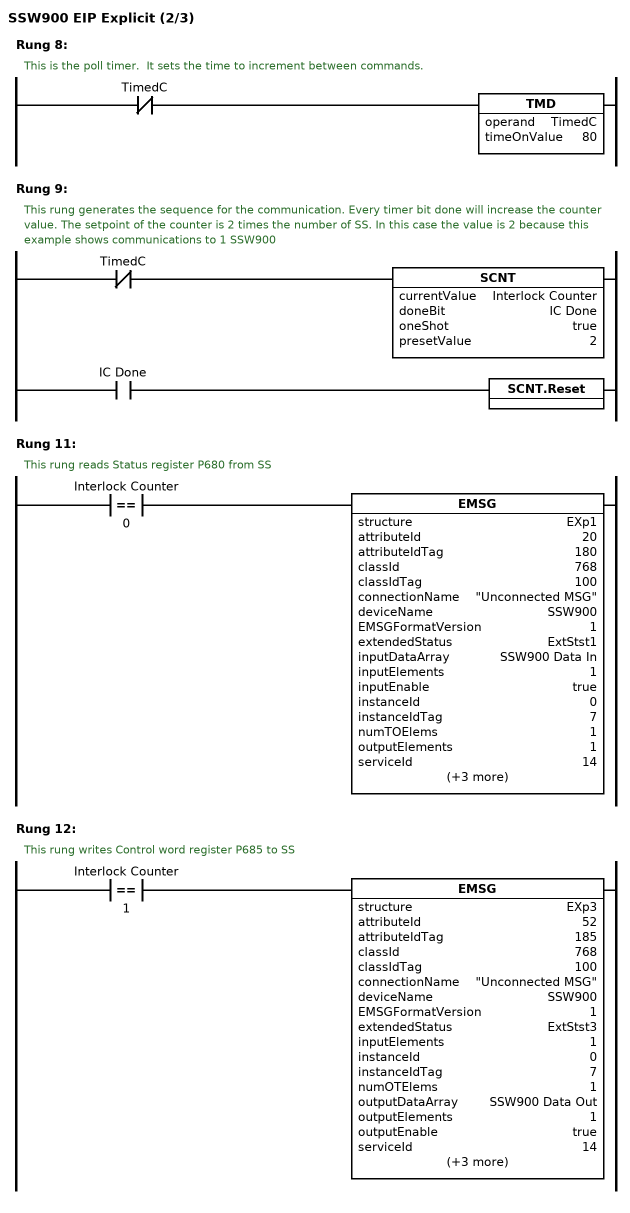
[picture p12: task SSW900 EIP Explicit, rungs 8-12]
Rung 8:
  // This is the poll timer.  It sets the time to increment between commands.
  NC(TimedC) TMD(TimedC, timeOnValue=80)
Rung 9:
  // This rung generates the sequence for the communication. Every timer bit done will increase the counter value. The setpoint of the counter is 2 times the number of SS. In this case the value is 2 because this example shows communications to 1 SSW900
  NC(TimedC) SCNT(currentValue='Interlock Counter', doneBit='IC Done', oneShot, presetValue=2)
  NO('IC Done') SCNT.Reset
Rung 11:
  // This rung reads Status register P680 from SS
  COMP('Interlock Counter' = 0)
    EMSG(structure=EXp1, attributeId=20, attributeIdTag=180, classId=768, classIdTag=100, connectionName="Unconnected MSG", deviceName=SSW900, EMSGFormatVersion=1, extendedStatus=ExtStst1, inputDataArray='SSW900 Data In', inputElements=1, inputEnable, instanceId=0, instanceIdTag=7, numTOElems=1, outputElements=1, serviceId=14, serviceIdTag=14, serviceName=Generic, useAttributeId)
Rung 12:
  // This rung writes Control word register P685 to SS
  COMP('Interlock Counter' = 1)
    EMSG(structure=EXp3, attributeId=52, attributeIdTag=185, classId=768, classIdTag=100, connectionName="Unconnected MSG", deviceName=SSW900, EMSGFormatVersion=1, extendedStatus=ExtStst3, inputElements=1, instanceId=0, instanceIdTag=7, numOTElems=1, outputDataArray='SSW900 Data Out', outputElements=1, outputEnable, serviceId=14, serviceIdTag=16, serviceName=Generic, useAttributeId)
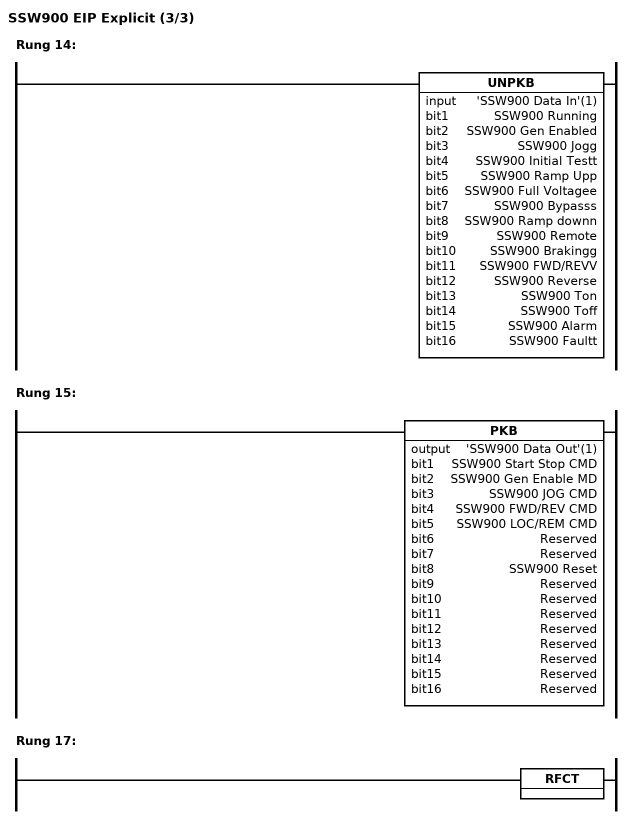
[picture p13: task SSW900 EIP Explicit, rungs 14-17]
Rung 14:
  UNPKB(input='SSW900 Data In'(1), bit1='SSW900 Running', bit2='SSW900 Gen Enabled', bit3='SSW900 Jogg', bit4='SSW900 Initial Testt', bit5='SSW900 Ramp Upp', bit6='SSW900 Full Voltagee', bit7='SSW900 Bypasss', bit8='SSW900 Ramp downn', bit9='SSW900 Remote', bit10='SSW900 Brakingg', bit11='SSW900 FWD/REVV', bit12='SSW900 Reverse', bit13='SSW900 Ton', bit14='SSW900 Toff', bit15='SSW900 Alarm', bit16='SSW900 Faultt')
Rung 15:
  PKB(output='SSW900 Data Out'(1), bit1='SSW900 Start Stop CMD', bit2='SSW900 Gen Enable MD', bit3='SSW900 JOG CMD', bit4='SSW900 FWD/REV CMD', bit5='SSW900 LOC/REM CMD', bit6=Reserved, bit7=Reserved, bit8='SSW900 Reset', bit9=Reserved, bit10=Reserved, bit11=Reserved, bit12=Reserved, bit13=Reserved, bit14=Reserved, bit15=Reserved, bit16=Reserved)
Rung 17:
  RFCT()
